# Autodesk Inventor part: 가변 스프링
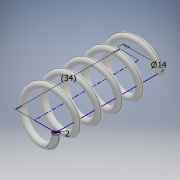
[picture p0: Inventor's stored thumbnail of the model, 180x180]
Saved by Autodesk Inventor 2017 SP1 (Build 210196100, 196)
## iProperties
Part Number: 가변 스프링
Material: 일반
Document SubType Name: Modeling
Designer: 00-00
Density: 1 g/cm^3
Appearance: 기본값
Author: 00-00
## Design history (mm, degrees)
sketch "스케치1"
  geometry: L1 (0, 0)-(7, 0); L2 (7, 0)-(7, 34); L3 (7, 34)-(0, 34); L4 (0, 34)-(0, 0); C1 r 1 at (7, 0)
  constraints: 8 end point, 2 parallel, 1 centre point, 1 coincident, 1 horizontal, 1 perpendicular
  dimensions: "d0" = 2 diameter of C1; "d1" = 14 diameter of L2 L4; "d2" = 34 distance of L3.end L1.start (derived)
feature "코일1" sketch "스케치1" pitch "d3" = 10; turns "d5" = 5; dims "d4" = 34 (= d2), "d6" = 0, angle "d7" = 90 deg, angle "d8" = 90 deg, "d9" = 0, "d10" = 0
sketch "스케치2"
  geometry: L1 (12.201, 34)-(-12.201, 34); L2 (-12.201, 34)-(-12.201, 0); L3 (-12.201, 0)-(12.201, 0); L4 (12.201, 0)-(12.201, 34); 2 further points
  constraints: 8 end point, 2 parallel, 1 coincident, 1 horizontal, 1 midpoint, 1 perpendicular
  dimensions: "d11" = 34 distance of L1.end L2.end (= d2); "d12" = 24.40191 distance of L1.start L1.end
extrude "돌출1" sketch "스케치2" stored distance "d13" = 18.75; taper "d14" = 0 deg
node "솔리드1"
